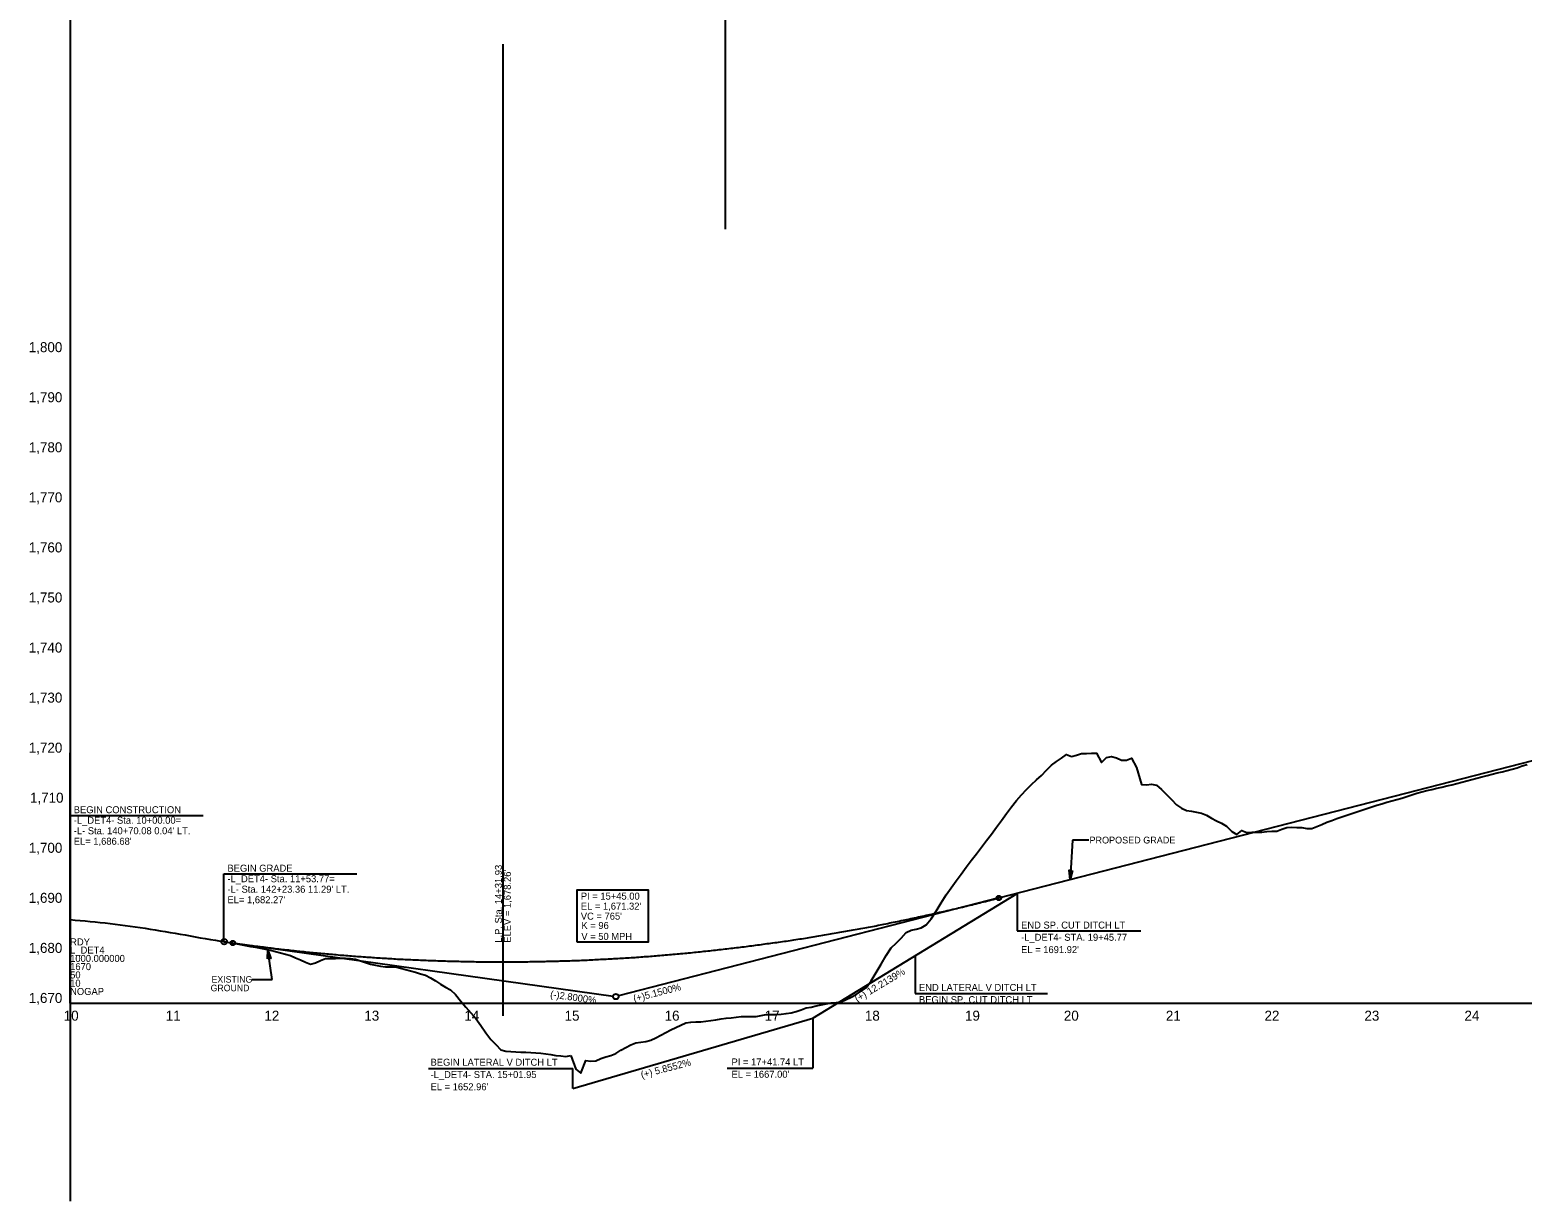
# Model space of a CAD drawing. Extents: x 498575 to 532350, y 405181 to 484585.
# Drawn here: x 505877 to 507367, y 434250 to 435420 of the extents above; entities that cross this region are included whole.
import ezdxf

# ---------------------------------------------------------------- set-up
doc = ezdxf.new("R2010")
doc.units = 0
for name, color, linetype in [('Exist Profile Cell', 7, 'Continuous'), ('Exist Vertical Profile Ground Line', 7, 'Continuous'), ('Exist Vertical Profile Horizontal Axis Label Major', 7, 'Continuous'), ('Exist Vertical Profile Vertical Axis Label', 7, 'Continuous'), ('Prop Grid Mask', 7, 'Continuous'), ('Prop PFL Text', 7, 'Continuous'), ('Prop Vertical Profile Curve Label', 7, 'Continuous'), ('Prop Vertical Profile Ditch Grade Left', 7, 'Continuous'), ('Prop Vertical Profile Ditch Grade Left Label', 7, 'Continuous'), ('Prop Vertical Profile Grade', 7, 'Continuous'), ('Prop Vertical Profile Grade Label', 7, 'Continuous'), ('Prop Vertical Profile Strip Grade', 7, 'Continuous'), ('Prop VPI Label', 7, 'Continuous'), ('Scratch_Level_5', 7, 'Continuous'), ('Typical Terminator CELL', 7, 'Continuous')]:
    doc.layers.add(name, color=color, linetype=linetype)

# ---------------------------------------------------------------- blocks, each defined once
blk = doc.blocks.new('TERMINATOR')
at = {"layer": 'Typical Terminator CELL'}
blk.add_lwpolyline([(-0.469, 0.081), (0, 0), (-0.471, -0.083), (-0.411, 0)], close=True, dxfattribs=at)

msp = doc.modelspace()

# ---------------------------------------------------------------- linework, layer by layer
at = {"layer": 'Exist Profile Cell'}
for p, q in [((505916.9, 435499.6), (505916.9, 434249.6)), ((505916.9, 434447.4), (505916.9, 434697.4)), ((505916.9, 434447.4), (509215.8, 434447.4)), ((505916.9, 434447.4), (505916.9, 434447.4))]:
    msp.add_line(p, q, dxfattribs=at)
at = {"layer": 'Exist Vertical Profile Ground Line'}
for points in [[(506416.9, 434395), (506421.9, 434381.6), (506426.9, 434377.6), (506431.9, 434390.1), (506436.9, 434389.3), (506441.9, 434389.9), (506446.9, 434392.1), (506451.9, 434393.7), (506456.9, 434395.1), (506461.9, 434397.2), (506466.9, 434400.4), (506471.9, 434403), (506476.9, 434405.8), (506481.9, 434407.9), (506486.9, 434408.3), (506491.9, 434409.2), (506496.9, 434410.6), (506501.9, 434412.9), (506506.9, 434415.5), (506511.9, 434418.1), (506516.9, 434420.7), (506521.9, 434423.1), (506526.9, 434425.4), (506531.9, 434427.6), (506536.9, 434428.4), (506541.9, 434428.6), (506546.9, 434428.9), (506551.9, 434429.5), (506556.9, 434430.1), (506561.9, 434430.8), (506566.9, 434431.6), (506571.9, 434432.3), (506576.9, 434432.8), (506581.9, 434433.4), (506586.9, 434434), (506591.9, 434434.2), (506596.9, 434434), (506601.9, 434434.2), (506606.9, 434435.2), (506611.9, 434436), (506616.9, 434436.2), (506621.9, 434436.2), (506626.9, 434436.4), (506631.9, 434437.1), (506636.9, 434437.7), (506641.9, 434439.2), (506646.9, 434440.9), (506651.9, 434442.6), (506656.9, 434443.5), (506661.9, 434444.7), (506666.9, 434445.7), (506671.9, 434446.8), (506676.9, 434447.7), (506681.9, 434448.2), (506686.9, 434448.8), (506691.9, 434451), (506696.9, 434453.4), (506701.9, 434456.1), (506706.9, 434459.5), (506711.9, 434462.8), (506716.9, 434469.8), (506721.9, 434477.9), (506726.9, 434486.5), (506731.9, 434495.1), (506736.9, 434502.5), (506741.9, 434507.2), (506746.9, 434512.3), (506751.9, 434518.1), (506756.9, 434520.2), (506761.9, 434521.3), (506766.9, 434522.8), (506771.9, 434525.8), (506776.9, 434531.6), (506781.9, 434539.3), (506786.9, 434547.5), (506791.9, 434555.7), (506796.9, 434562.7), (506801.9, 434569.5), (506806.9, 434576.3), (506811.9, 434583.1), (506816.9, 434589.9), (506821.9, 434596.5), (506826.9, 434603.2), (506831.9, 434609.8), (506836.9, 434616.3), (506841.9, 434623.1), (506846.9, 434630), (506851.9, 434636.8), (506856.9, 434643.4), (506861.9, 434649.8), (506866.9, 434655.5), (506871.9, 434660.9), (506876.9, 434665.9), (506881.9, 434670.3), (506886.9, 434674.9), (506891.9, 434680), (506896.9, 434685.1), (506901.9, 434688.7), (506906.9, 434692.2), (506911.9, 434695.6), (506916.9, 434693.7)], [(506916.9, 434693.7), (506921.9, 434695.1), (506926.9, 434696.7), (506931.9, 434696.8), (506936.9, 434697), (506941.9, 434697), (506946.9, 434687.9), (506951.9, 434692.9), (506956.9, 434693.9), (506961.9, 434692.6), (506966.9, 434690), (506971.9, 434690.1), (506976.9, 434692), (506981.9, 434682.7), (506986.9, 434665.8), (506991.9, 434665.6), (506996.9, 434666.2), (507001.9, 434665.1), (507006.9, 434660.9), (507011.9, 434655.8), (507016.9, 434650.7), (507021.9, 434645.6), (507026.9, 434642.2), (507031.9, 434639.7), (507036.9, 434639), (507041.9, 434638.3), (507046.9, 434637.1), (507051.9, 434635.2), (507056.9, 434632.3), (507061.9, 434629.4), (507066.9, 434627.1), (507071.9, 434624.3), (507076.9, 434618.8), (507081.9, 434616), (507086.9, 434619.7), (507091.9, 434617.8), (507096.9, 434618.1), (507101.9, 434618.1), (507106.9, 434618.1), (507111.9, 434618.9), (507116.9, 434619.2), (507121.9, 434619.2), (507126.9, 434621.2), (507131.9, 434622.8), (507136.9, 434623.3), (507141.9, 434623), (507146.9, 434622.8), (507151.9, 434621.8), (507156.9, 434621.9), (507161.9, 434623.8), (507166.9, 434625.8), (507171.9, 434628.1), (507176.9, 434630), (507181.9, 434631.8), (507186.9, 434633.5), (507191.9, 434635.2), (507196.9, 434636.8), (507201.9, 434638.5), (507206.9, 434640.2), (507211.9, 434641.8), (507216.9, 434643.5), (507221.9, 434645), (507226.9, 434646.5), (507231.9, 434648), (507236.9, 434649.5), (507241.9, 434650.9), (507246.9, 434652.3), (507251.9, 434653.7), (507256.9, 434655.4), (507261.9, 434657.1), (507266.9, 434658.4), (507271.9, 434659.7), (507276.9, 434660.7), (507281.9, 434662), (507286.9, 434663.3), (507291.9, 434664.5), (507296.9, 434665.6), (507301.9, 434666.9), (507306.9, 434668.1), (507311.9, 434669.4), (507316.9, 434670.7), (507321.9, 434672), (507326.9, 434673.4), (507331.9, 434674.7), (507336.9, 434676), (507341.9, 434677.3), (507346.9, 434678.6), (507351.9, 434679.9), (507356.9, 434681.2), (507361.9, 434682.6), (507366.9, 434684.4), (507371.9, 434685.7)], [(505916.9, 434530.8), (505921.9, 434530.4), (505926.9, 434530), (505931.9, 434529.5), (505936.9, 434529.1), (505941.9, 434528.6), (505946.9, 434528.1), (505951.9, 434527.5), (505956.9, 434526.9), (505961.9, 434526.3), (505966.9, 434525.7), (505971.9, 434525), (505976.9, 434524.4), (505981.9, 434523.7), (505986.9, 434522.9), (505991.9, 434522.2), (505996.9, 434521.4), (506001.9, 434520.6), (506006.9, 434519.8), (506011.9, 434518.9), (506016.9, 434518.1), (506021.9, 434517.3), (506026.9, 434516.4), (506031.9, 434515.5), (506036.9, 434514.6), (506041.9, 434513.7), (506046.9, 434512.8), (506051.9, 434511.9), (506056.9, 434511.1), (506061.9, 434510.2), (506066.9, 434509.3), (506071.9, 434508.6), (506076.9, 434507.7), (506081.9, 434506.9), (506086.9, 434505.9), (506091.9, 434504.9), (506096.9, 434504.1), (506101.9, 434503.2), (506106.9, 434502.3), (506111.9, 434501.3), (506116.9, 434500.2), (506121.9, 434499), (506126.9, 434497.7), (506131.9, 434496.4), (506136.9, 434494.9), (506141.9, 434492.7), (506146.9, 434490.6), (506151.9, 434488.3), (506156.9, 434486.2), (506161.9, 434487.8), (506166.9, 434490), (506171.9, 434492), (506176.9, 434492.1), (506181.9, 434492.1), (506186.9, 434492.5), (506191.9, 434492.5), (506196.9, 434491.9), (506201.9, 434491.3), (506206.9, 434489.7), (506211.9, 434487.9), (506216.9, 434486.2), (506221.9, 434485.4), (506226.9, 434484.5), (506231.9, 434483.7), (506236.9, 434483.6), (506241.9, 434483.6), (506246.9, 434482.4), (506251.9, 434481.1), (506256.9, 434479.8), (506261.9, 434478.4), (506266.9, 434476.8), (506271.9, 434475.2), (506276.9, 434472.6), (506281.9, 434469.7), (506286.9, 434466.5), (506291.9, 434463.3), (506296.9, 434460.6), (506301.9, 434456), (506306.9, 434449.7), (506311.9, 434443.5), (506316.9, 434437.8), (506321.9, 434432.1), (506326.9, 434425.1), (506331.9, 434417.7), (506336.9, 434411.1), (506341.9, 434406), (506346.9, 434400.9), (506351.9, 434399.3), (506356.9, 434399), (506361.9, 434398.7), (506366.9, 434398.6), (506371.9, 434398.4), (506376.9, 434398.1), (506381.9, 434397.8), (506386.9, 434397.4), (506391.9, 434396.7), (506396.9, 434396), (506401.9, 434395.2), (506406.9, 434394.8), (506411.9, 434394.2), (506416.9, 434395)]]:
    msp.add_lwpolyline(points, dxfattribs=at)
at = {"layer": 'Prop Grid Mask'}
msp.add_lwpolyline([(506423, 434508.6), (506494.4, 434508.6), (506494.4, 434560.3), (506423, 434560.3)], close=True, dxfattribs=at)
at = {"layer": 'Prop PFL Text'}
for p, q in [((506918.1, 434610.1), (506915.6, 434570.8)), ((506934.1, 434610.1), (506918.1, 434610.1)), ((506118.6, 434471.2), (506114.4, 434500.8)), ((506098.2, 434471.2), (506118.6, 434471.2))]:
    msp.add_line(p, q, dxfattribs=at)
msp.add_lwpolyline([(506114.1, 434491.6), (506114.4, 434500.8), (506117.3, 434492), (506115.5, 434492.9)], close=True, dxfattribs=at)
at = {"layer": 'Prop Vertical Profile Curve Label'}
for centre in [(506844.4, 434552.5), (506079.4, 434507.5)]:
    msp.add_circle(centre, 2.25, dxfattribs=at)
at = {"layer": 'Prop Vertical Profile Ditch Grade Left'}
msp.add_lwpolyline([(506418.9, 434362.2), (506658.7, 434432.4), (506862.7, 434557)], dxfattribs=at)
at = {"layer": 'Prop Vertical Profile Ditch Grade Left Label'}
for p, q in [((506862.7, 434557), (506862.7, 434519.5)), ((506862.7, 434519.5), (506986.2, 434519.5)), ((506760.7, 434494.7), (506760.7, 434457.2)), ((506760.7, 434457.2), (506893, 434457.2)), ((506658.7, 434432.4), (506658.7, 434382.5)), ((506274.9, 434382.2), (506418.9, 434382.2)), ((506418.9, 434362.2), (506418.9, 434382.2)), ((506572.9, 434382.5), (506658.7, 434382.5))]:
    msp.add_line(p, q, dxfattribs=at)
at = {"layer": 'Prop Vertical Profile Grade'}
for p, q in [((506844.4, 434552.5), (508116.9, 434880.1)), ((506070.7, 434508.8), (506079.4, 434507.5))]:
    msp.add_line(p, q, dxfattribs=at)
msp.add_spline([(506079.4, 434507.5), (506094.7, 434505.4), (506110, 434503.5), (506125.3, 434501.6), (506140.6, 434499.9), (506155.9, 434498.3), (506171.2, 434496.9), (506186.5, 434495.5), (506201.8, 434494.3), (506217.1, 434493.2), (506232.4, 434492.2), (506247.7, 434491.3), (506263, 434490.6), (506278.3, 434490), (506293.6, 434489.5), (506308.9, 434489.1), (506324.2, 434488.8), (506339.5, 434488.7), (506354.8, 434488.7), (506370.1, 434488.8), (506385.4, 434489), (506400.7, 434489.4), (506416, 434489.8), (506431.3, 434490.4), (506446.6, 434491.2), (506461.9, 434492), (506477.2, 434492.9), (506492.5, 434494), (506507.8, 434495.2), (506523.1, 434496.6), (506538.4, 434498), (506553.7, 434499.6), (506569, 434501.3), (506584.3, 434503.1), (506599.6, 434505), (506614.9, 434507.1), (506630.2, 434509.2), (506645.5, 434511.5), (506660.8, 434514), (506676.1, 434516.5), (506691.4, 434519.2), (506706.7, 434521.9), (506722, 434524.8), (506737.3, 434527.9), (506752.6, 434531), (506767.9, 434534.3), (506783.2, 434537.7), (506798.5, 434541.2), (506813.8, 434544.8), (506829.1, 434548.6), (506844.4, 434552.5)], degree=3, dxfattribs=at)
at = {"layer": 'Prop Vertical Profile Strip Grade'}
msp.add_line((506348.9, 434591.5), (506348.9, 434488.7), dxfattribs=at)
at = {"layer": 'Prop VPI Label'}
for p, q in [((505916.9, 434634.9), (506049.7, 434634.9)), ((505916.9, 434634.9), (505916.9, 434530.8)), ((506070.5, 434508.8), (506070.5, 434576.5)), ((506070.5, 434576.5), (506203.2, 434576.5)), ((506844.4, 434552.5), (506464.6, 434454.7)), ((506079.4, 434507.5), (506459.2, 434454.4))]:
    msp.add_line(p, q, dxfattribs=at)
for centre in [(506070.7, 434508.8), (506461.9, 434454)]:
    msp.add_circle(centre, 2.75, dxfattribs=at)
at = {"layer": 'Scratch_Level_5'}
for p, q in [((506570.9, 436190.7), (506570.9, 435220.3)), ((506348.9, 435405.2), (506348.9, 434434.9))]:
    msp.add_line(p, q, dxfattribs=at)

# ---------------------------------------------------------------- block references
at = {"layer": 'Prop PFL Text', "xscale": 20, "yscale": 19.999999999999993, "rotation": -93.70508386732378}
msp.add_blockref('TERMINATOR', (506915.6, 434570.8), dxfattribs=at)

# ---------------------------------------------------------------- texts
at = {"layer": 'Exist Profile Cell'}
for s, p in [('RDY', (505916.9, 434505.1)), ('L_DET4', (505916.9, 434496.9)), ('1000.000000', (505916.9, 434488.6)), ('1670', (505916.9, 434480.4)), ('50', (505916.9, 434472.1)), ('10', (505916.9, 434463.9)), ('NOGAP', (505916.9, 434455.6))]:
    msp.add_text(s, height=7, dxfattribs=at).set_placement(p)
at = {"layer": 'Exist Vertical Profile Horizontal Axis Label Major'}
for s, p in [('10', (505910.5, 434429.9)), ('11', (506012.4, 434429.9)), ('12', (506110.9, 434429.9)), ('13', (506210.7, 434429.9)), ('14', (506310.6, 434429.9)), ('15', (506410.7, 434429.9)), ('16', (506510.6, 434429.9)), ('17', (506610.5, 434429.9)), ('18', (506710.6, 434429.9)), ('19', (506810.6, 434429.9)), ('20', (506909.3, 434429.9)), ('21', (507011.2, 434429.9)), ('22', (507109.7, 434429.9)), ('23', (507209.5, 434429.9)), ('24', (507309.4, 434429.9))]:
    msp.add_text(s, height=10, dxfattribs=at).set_placement(p)
at = {"layer": 'Exist Vertical Profile Vertical Axis Label'}
for s, p in [('1,800', (505875.6, 435097.6)), ('1,790', (505875.6, 435047.6)), ('1,780', (505875.6, 434997.6)), ('1,770', (505875.6, 434947.6)), ('1,760', (505875.6, 434897.6)), ('1,750', (505875.6, 434847.6)), ('1,740', (505875.6, 434797.6)), ('1,730', (505875.6, 434747.6)), ('1,720', (505875.6, 434697.6)), ('1,710', (505876.8, 434647.6)), ('1,700', (505875.6, 434597.6)), ('1,690', (505875.6, 434547.6)), ('1,680', (505875.6, 434497.6)), ('1,670', (505875.6, 434447.6))]:
    msp.add_text(s, height=10, dxfattribs=at).set_placement(p)
at = {"layer": 'Prop PFL Text'}
for s, height, p in [('PROPOSED GRADE', 6.75, (506934.9, 434606.9)), ('EXISTING', 6.52, (506058.1, 434467.9)), ('GROUND', 6.52, (506057.2, 434459.3))]:
    msp.add_text(s, height=height, dxfattribs=at).set_placement(p)
at = {"layer": 'Prop Vertical Profile Curve Label'}
for s, p in [("VC = 765'", (506426.9, 434530.8)), ('V = 50 MPH ', (506427.4, 434510.6)), ('K = 96', (506427.5, 434521.5))]:
    msp.add_text(s, height=7, dxfattribs=at).set_placement(p)
at = {"layer": 'Prop Vertical Profile Ditch Grade Left Label'}
for s, rotation, p in [('-L_DET4- STA. 19+45.77', 360, (506866.6, 434509.7)), ('END SP. CUT DITCH LT', 360, (506866.6, 434521.9)), ("EL = 1691.92'", 360, (506866.6, 434497.4)), ('(+) 12.2139%', 30.745, (506703, 434448.1)), ('END LATERAL V DITCH LT', 360, (506764.6, 434459.6)), ('BEGIN SP. CUT DITCH LT', 360, (506764.6, 434447.4)), ('BEGIN LATERAL V DITCH LT', 360, (506276.8, 434384.9)), ('(+) 5.8552%', 14.7074, (506487.8, 434372.3)), ('PI = 17+41.74 LT', 360, (506577.4, 434385.2)), ('-L_DET4- STA. 15+01.95', 360, (506276.8, 434372.6)), ("EL = 1652.96'", 360, (506276.8, 434360.4)), ("EL = 1667.00'", 360, (506577.4, 434372.9))]:
    msp.add_text(s, height=7, rotation=rotation, dxfattribs=at).set_placement(p)
at = {"layer": 'Prop Vertical Profile Grade Label'}
for s, rotation, p in [('(-)2.8000%', 352.0304, (506396, 434453.1)), ('(+)5.1500%', 14.44, (506480.3, 434448.4))]:
    msp.add_text(s, height=7, rotation=rotation, dxfattribs=at).set_placement(p)
at = {"layer": 'Prop Vertical Profile Strip Grade'}
for s, p in [('L.P. Sta. 14+31.93', (506348.1, 434507.8)), ("ELEV = 1,678.26'", (506357, 434507.8))]:
    msp.add_text(s, height=7, rotation=90, dxfattribs=at).set_placement(p)
at = {"layer": 'Prop VPI Label'}
for s, p in [('-L_DET4- Sta. 10+00.00=', (505920.5, 434626.6)), ('BEGIN CONSTRUCTION', (505920.5, 434637.1)), ("-L- Sta. 140+70.08 0.04' LT.", (505920.5, 434616.1)), ("EL= 1,686.68'", (505920.5, 434605.6)), ('-L_DET4- Sta. 11+53.77=', (506074, 434568.2)), ('BEGIN GRADE', (506074, 434578.7)), ("-L- Sta. 142+23.36 11.29' LT.", (506074, 434557.7)), ("EL= 1,682.27'", (506074, 434547.2)), ('PI = 15+45.00', (506426.9, 434550.8)), ("EL = 1,671.32'", (506426.9, 434540.8))]:
    msp.add_text(s, height=7, dxfattribs=at).set_placement(p)

doc.saveas('drawing.dxf')
